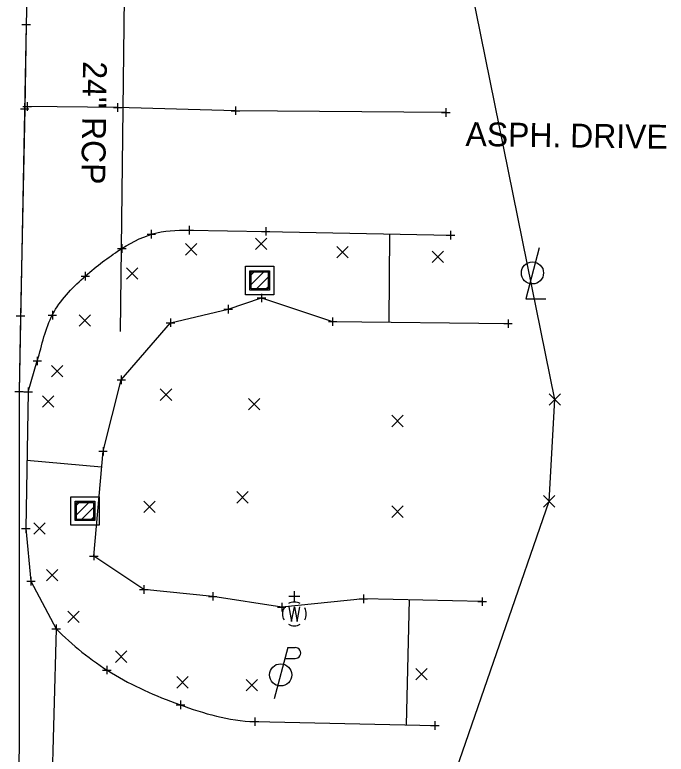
# Model space of a CAD drawing. Extents: x 1392719 to 1392850, y 437833 to 438309.
# Drawn here: x 1392773.1 to 1392849.5, y 437931.1 to 438017.9 of the extents above; entities that cross this region are included whole.
import ezdxf

# ---------------------------------------------------------------- set-up
doc = ezdxf.new("R2010")
doc.units = 0
for name, color, linetype in [('_CIVIL_CONSTRUCTION', 7, 'Continuous'), ('DR_X_Storm_Sewer', 7, 'Continuous'), ('DT_X_Slope_Break_Line', 7, 'Continuous'), ('PV_P_Curb_Ramp', 7, 'Continuous'), ('PV_X_COP', 7, 'Continuous'), ('PV_X_EOP', 7, 'Continuous'), ('RD_P_Fence', 7, 'Continuous'), ('RW_X_Fee_RW', 7, 'Continuous'), ('SC_Scratch6', 7, 'Continuous'), ('SH_Data', 7, 'Continuous'), ('SV_X_Mon_Cells_Found', 7, 'Continuous'), ('SV_X_Terrain_Boundary', 7, 'Continuous'), ('SV_X_Toe_of_Slope', 7, 'Continuous'), ('TX_X_20', 7, 'Continuous')]:
    doc.layers.add(name, color=color, linetype=linetype)

msp = doc.modelspace()

# ---------------------------------------------------------------- linework, layer by layer
at = {"layer": '_CIVIL_CONSTRUCTION'}
for p, q in [((1392805.915, 437948.997), (1392805.915, 437950.269)), ((1392806.55, 437949.634), (1392805.278, 437949.634)), ((1392805.915, 437947.597), (1392805.915, 437947.597))]:
    msp.add_line(p, q, dxfattribs=at)
msp.add_lwpolyline([(1392805.278, 437948.417), (1392805.597, 437946.694), (1392805.915, 437948.417), (1392806.235, 437946.694), (1392806.552, 437948.417)], dxfattribs=at)
for start, end in [(60.01836, 120.01574), (150.01836, 209.98164), (330.01836, 29.98164), (239.98426, 299.98164)]:
    msp.add_arc((1392805.915, 437947.599), 1.4, start, end, dxfattribs=at)
at = {"layer": 'DR_X_Storm_Sewer'}
msp.add_line((1392785.965, 438020.942), (1392785.478, 437980.73), dxfattribs=at)
at = {"layer": 'DT_X_Slope_Break_Line'}
for p, q in [((1392817.078, 437992.184), (1392816.984, 437981.814)), ((1392774.538, 437965.627), (1392783.305, 437964.843)), ((1392819.092, 437934.576), (1392819.418, 437949.247))]:
    msp.add_line(p, q, dxfattribs=at)
at = {"layer": 'PV_P_Curb_Ramp'}
for p, q in [((1392805.161, 437943.652), (1392803.554, 437937.652)), ((1392805.161, 437943.652), (1392806.011, 437943.652)), ((1392804.819, 437942.377), (1392806.011, 437942.377))]:
    msp.add_line(p, q, dxfattribs=at)
msp.add_circle((1392804.304, 437940.452), 1.3, dxfattribs=at)
msp.add_arc((1392806.023, 437943.014), 0.638, 268.8767, 91.1233, dxfattribs=at)
at = {"layer": 'PV_X_COP'}
msp.add_lwpolyline([(1392823.699, 438006.407), (1392799.009, 438006.632), (1392785.176, 438007.01), (1392774.572, 438007.13)], dxfattribs=at)
at = {"layer": 'PV_X_EOP'}
for p, q in [((1392793.579, 437992.61), (1392802.551, 437992.477)), ((1392802.551, 437992.477), (1392824.235, 437992.039)), ((1392774.688, 437973.669), (1392775.756, 437977.274)), ((1392801.259, 437934.966), (1392822.388, 437934.504))]:
    msp.add_line(p, q, dxfattribs=at)
msp.add_lwpolyline([(1392775.84, 438041.527), (1392775.139, 438041.438), (1392774.596, 438023.273), (1392774.455, 438016.732), (1392774.273, 438006.861), (1392773.79, 437982.569), (1392773.613, 437973.697), (1392774.676, 437973.647), (1392774.4, 437957.607), (1392775.011, 437951.431), (1392777.984, 437945.863), (1392777.432, 437925.849), (1392776.728, 437901.157), (1392774.065, 437895.811), (1392773.599, 437888.633)], dxfattribs=at)
for points in [[(1392775.756, 437977.274), (1392776.32, 437979.177), (1392777.048, 437982.962), (1392781.186, 437987.227), (1392785.154, 437990.263), (1392789.266, 437992.519), (1392792.014, 437992.633), (1392793.579, 437992.61)], [(1392777.977, 437945.834), (1392779.814, 437944.001), (1392784.232, 437940.353), (1392792.299, 437936.832), (1392798.232, 437935.032), (1392801.259, 437934.966)]]:
    msp.add_open_spline(points, degree=3, dxfattribs=at)
at = {"layer": 'RD_P_Fence'}
for p, q in [((1392801.365, 437990.332), (1392802.699, 437991.667)), ((1392801.365, 437991.667), (1392802.699, 437990.332)), ((1392793.139, 437989.7), (1392794.473, 437991.035)), ((1392793.139, 437991.035), (1392794.473, 437989.7)), ((1392810.899, 437989.363), (1392812.233, 437990.698)), ((1392810.899, 437990.698), (1392812.233, 437989.363)), ((1392822.068, 437988.807), (1392823.402, 437990.142)), ((1392822.068, 437990.142), (1392823.402, 437988.807)), ((1392786.218, 437986.88), (1392787.552, 437988.215)), ((1392786.218, 437988.215), (1392787.552, 437986.88)), ((1392780.663, 437981.34), (1392781.997, 437982.674)), ((1392780.663, 437982.674), (1392781.997, 437981.34)), ((1392777.426, 437975.426), (1392778.76, 437976.76)), ((1392777.426, 437976.76), (1392778.76, 437975.426)), ((1392790.187, 437972.652), (1392791.521, 437973.987)), ((1392790.187, 437973.987), (1392791.521, 437972.652)), ((1392835.797, 437972.075), (1392837.131, 437973.41)), ((1392835.797, 437973.41), (1392837.131, 437972.075)), ((1392776.361, 437971.85), (1392777.695, 437973.184)), ((1392776.361, 437973.184), (1392777.695, 437971.85)), ((1392800.536, 437971.54), (1392801.87, 437972.874)), ((1392800.536, 437972.874), (1392801.87, 437971.54)), ((1392817.347, 437969.562), (1392818.681, 437970.896)), ((1392817.347, 437970.896), (1392818.681, 437969.562)), ((1392799.17, 437960.611), (1392800.504, 437961.945)), ((1392799.17, 437961.945), (1392800.504, 437960.611)), ((1392835.157, 437960.142), (1392836.491, 437961.477)), ((1392835.157, 437961.477), (1392836.491, 437960.142)), ((1392788.263, 437959.503), (1392789.597, 437960.837)), ((1392788.263, 437960.837), (1392789.597, 437959.503)), ((1392817.334, 437958.927), (1392818.668, 437960.263)), ((1392817.334, 437960.263), (1392818.668, 437958.927)), ((1392775.352, 437956.946), (1392776.686, 437958.281)), ((1392775.352, 437958.281), (1392776.686, 437956.946)), ((1392776.837, 437951.494), (1392778.171, 437952.829)), ((1392776.837, 437952.829), (1392778.171, 437951.494)), ((1392779.335, 437946.601), (1392780.669, 437947.935)), ((1392779.335, 437947.935), (1392780.669, 437946.601)), ((1392784.929, 437941.916), (1392786.263, 437943.252)), ((1392784.929, 437943.252), (1392786.263, 437941.916)), ((1392820.167, 437939.873), (1392821.501, 437941.209)), ((1392820.167, 437941.209), (1392821.501, 437939.873)), ((1392792.136, 437938.911), (1392793.47, 437940.247)), ((1392792.136, 437940.247), (1392793.47, 437938.911)), ((1392800.268, 437938.584), (1392801.602, 437939.918)), ((1392800.268, 437939.918), (1392801.602, 437938.584))]:
    msp.add_line(p, q, dxfattribs=at)
at = {"layer": 'RW_X_Fee_RW'}
for p, q in [((1392800.702, 437986.102), (1392802.461, 437987.861)), ((1392800.702, 437987.233), (1392801.33, 437987.861)), ((1392801.301, 437985.569), (1392802.994, 437987.262)), ((1392802.432, 437985.569), (1392802.994, 437986.131)), ((1392780.209, 437959.074), (1392781.968, 437960.833)), ((1392780.209, 437960.205), (1392780.837, 437960.833)), ((1392780.808, 437958.541), (1392782.501, 437960.234)), ((1392781.939, 437958.541), (1392782.501, 437959.103))]:
    msp.add_line(p, q, dxfattribs=at)
for points in [[(1392800.181, 437988.382), (1392803.515, 437988.382), (1392803.515, 437985.048), (1392800.181, 437985.048)], [(1392800.702, 437987.861), (1392802.994, 437987.861), (1392802.994, 437985.569), (1392800.702, 437985.569)], [(1392800.848, 437987.715), (1392802.848, 437987.715), (1392802.848, 437985.715), (1392800.848, 437985.715)], [(1392779.688, 437961.354), (1392783.022, 437961.354), (1392783.022, 437958.02), (1392779.688, 437958.02)], [(1392780.209, 437960.833), (1392782.501, 437960.833), (1392782.501, 437958.541), (1392780.209, 437958.541)], [(1392780.355, 437960.687), (1392782.355, 437960.687), (1392782.355, 437958.687), (1392780.355, 437958.687)]]:
    msp.add_lwpolyline(points, close=True, dxfattribs=at)
at = {"layer": 'SC_Scratch6'}
for p, q in [((1392773.955, 438016.732), (1392774.955, 438016.732)), ((1392774.455, 438017.232), (1392774.455, 438016.232)), ((1392774.455, 438016.732), (1392774.455, 438016.732)), ((1392774.072, 438007.13), (1392775.072, 438007.13)), ((1392774.273, 438007.361), (1392774.273, 438006.361)), ((1392774.572, 438007.63), (1392774.572, 438006.63)), ((1392774.572, 438007.13), (1392774.572, 438007.13)), ((1392785.176, 438007.51), (1392785.176, 438006.51)), ((1392799.009, 438007.132), (1392799.009, 438006.132)), ((1392773.773, 438006.861), (1392774.773, 438006.861)), ((1392774.273, 438006.861), (1392774.273, 438006.861)), ((1392784.676, 438007.01), (1392785.676, 438007.01)), ((1392785.176, 438007.01), (1392785.176, 438007.01)), ((1392798.509, 438006.632), (1392799.509, 438006.632)), ((1392799.009, 438006.632), (1392799.009, 438006.632)), ((1392823.199, 438006.407), (1392824.199, 438006.407)), ((1392823.699, 438006.907), (1392823.699, 438005.907)), ((1392823.699, 438006.407), (1392823.699, 438006.407)), ((1392789.13, 437992.647), (1392789.13, 437991.647)), ((1392793.079, 437992.61), (1392794.079, 437992.61)), ((1392793.579, 437993.11), (1392793.579, 437992.11)), ((1392793.579, 437992.61), (1392793.579, 437992.61)), ((1392802.051, 437992.477), (1392803.051, 437992.477)), ((1392802.551, 437992.977), (1392802.551, 437991.977)), ((1392802.551, 437992.477), (1392802.551, 437992.477)), ((1392824.235, 437992.539), (1392824.235, 437991.539)), ((1392788.63, 437992.147), (1392789.63, 437992.147)), ((1392789.13, 437992.147), (1392789.13, 437992.147)), ((1392823.735, 437992.039), (1392824.735, 437992.039)), ((1392824.235, 437992.039), (1392824.235, 437992.039)), ((1392785.678, 437990.96), (1392785.678, 437989.96)), ((1392785.178, 437990.46), (1392786.178, 437990.46)), ((1392785.678, 437990.46), (1392785.678, 437990.46)), ((1392780.889, 437987.218), (1392781.889, 437987.218)), ((1392781.389, 437987.718), (1392781.389, 437986.718)), ((1392781.389, 437987.218), (1392781.389, 437987.218)), ((1392801.556, 437984.666), (1392802.556, 437984.666)), ((1392802.056, 437985.166), (1392802.056, 437984.166)), ((1392802.056, 437984.666), (1392802.056, 437984.666)), ((1392798.139, 437983.856), (1392798.139, 437982.856)), ((1392773.79, 437983.069), (1392773.79, 437982.069)), ((1392777.525, 437983.153), (1392777.525, 437982.153)), ((1392797.639, 437983.356), (1392798.639, 437983.356)), ((1392798.139, 437983.356), (1392798.139, 437983.356)), ((1392773.29, 437982.569), (1392774.29, 437982.569)), ((1392773.79, 437982.569), (1392773.79, 437982.569)), ((1392777.025, 437982.653), (1392778.025, 437982.653)), ((1392777.525, 437982.653), (1392777.525, 437982.653)), ((1392791.391, 437982.259), (1392791.391, 437981.259)), ((1392810.405, 437982.388), (1392810.405, 437981.388)), ((1392830.988, 437982.155), (1392830.988, 437981.155)), ((1392790.891, 437981.759), (1392791.891, 437981.759)), ((1392791.391, 437981.759), (1392791.391, 437981.759)), ((1392809.905, 437981.888), (1392810.905, 437981.888)), ((1392810.405, 437981.888), (1392810.405, 437981.888)), ((1392830.488, 437981.655), (1392831.488, 437981.655)), ((1392830.988, 437981.655), (1392830.988, 437981.655)), ((1392775.756, 437977.774), (1392775.756, 437976.774)), ((1392775.256, 437977.274), (1392776.256, 437977.274)), ((1392775.756, 437977.274), (1392775.756, 437977.274)), ((1392785.11, 437975.049), (1392786.11, 437975.049)), ((1392785.61, 437975.549), (1392785.61, 437974.549)), ((1392785.61, 437975.049), (1392785.61, 437975.049)), ((1392773.613, 437974.197), (1392773.613, 437973.197)), ((1392774.676, 437974.147), (1392774.676, 437973.147)), ((1392774.688, 437974.169), (1392774.688, 437973.169)), ((1392773.113, 437973.697), (1392774.113, 437973.697)), ((1392773.613, 437973.697), (1392773.613, 437973.697)), ((1392774.176, 437973.647), (1392775.176, 437973.647)), ((1392774.188, 437973.669), (1392775.188, 437973.669)), ((1392774.676, 437973.647), (1392774.676, 437973.647)), ((1392774.688, 437973.669), (1392774.688, 437973.669)), ((1392783.468, 437967.179), (1392783.468, 437966.179)), ((1392782.968, 437966.679), (1392783.968, 437966.679)), ((1392783.468, 437966.679), (1392783.468, 437966.679)), ((1392774.4, 437958.107), (1392774.4, 437957.107)), ((1392773.9, 437957.607), (1392774.9, 437957.607)), ((1392774.4, 437957.607), (1392774.4, 437957.607)), ((1392781.878, 437954.39), (1392782.878, 437954.39)), ((1392782.378, 437954.89), (1392782.378, 437953.89)), ((1392782.378, 437954.39), (1392782.378, 437954.39)), ((1392775.011, 437951.931), (1392775.011, 437950.931)), ((1392774.511, 437951.431), (1392775.511, 437951.431)), ((1392775.011, 437951.431), (1392775.011, 437951.431)), ((1392788.261, 437950.964), (1392788.261, 437949.964)), ((1392787.761, 437950.464), (1392788.761, 437950.464)), ((1392788.261, 437950.464), (1392788.261, 437950.464)), ((1392796.338, 437950.164), (1392796.338, 437949.164)), ((1392814.013, 437949.876), (1392814.013, 437948.876)), ((1392795.838, 437949.664), (1392796.838, 437949.664)), ((1392796.338, 437949.664), (1392796.338, 437949.664)), ((1392813.513, 437949.376), (1392814.513, 437949.376)), ((1392814.013, 437949.376), (1392814.013, 437949.376)), ((1392827.451, 437949.043), (1392828.451, 437949.043)), ((1392827.951, 437949.543), (1392827.951, 437948.543)), ((1392827.951, 437949.043), (1392827.951, 437949.043)), ((1392803.928, 437948.39), (1392804.928, 437948.39)), ((1392804.428, 437948.89), (1392804.428, 437947.89)), ((1392804.428, 437948.39), (1392804.428, 437948.39)), ((1392777.984, 437946.363), (1392777.984, 437945.363)), ((1392777.477, 437945.834), (1392778.477, 437945.834)), ((1392777.484, 437945.863), (1392778.484, 437945.863)), ((1392777.977, 437946.334), (1392777.977, 437945.334)), ((1392777.977, 437945.834), (1392777.977, 437945.834)), ((1392777.984, 437945.863), (1392777.984, 437945.863)), ((1392783.918, 437941.521), (1392783.918, 437940.521)), ((1392783.418, 437941.021), (1392784.418, 437941.021)), ((1392783.918, 437941.021), (1392783.918, 437941.021)), ((1392792.051, 437936.933), (1392793.051, 437936.933)), ((1392792.551, 437937.433), (1392792.551, 437936.433)), ((1392792.551, 437936.933), (1392792.551, 437936.933)), ((1392801.259, 437935.466), (1392801.259, 437934.466)), ((1392800.759, 437934.966), (1392801.759, 437934.966)), ((1392801.259, 437934.966), (1392801.259, 437934.966)), ((1392821.888, 437934.504), (1392822.888, 437934.504)), ((1392822.388, 437935.004), (1392822.388, 437934.004)), ((1392822.388, 437934.504), (1392822.388, 437934.504))]:
    msp.add_line(p, q, dxfattribs=at)
at = {"layer": 'SH_Data'}
msp.add_lwpolyline([(1392834.64, 437990.554), (1392833.065, 437984.569), (1392835.428, 437984.569)], dxfattribs=at)
msp.add_circle((1392833.853, 437987.601), 1.3, dxfattribs=at)
at = {"layer": 'SV_X_Mon_Cells_Found'}
for p, q in [((1392801.848, 437988.382), (1392801.848, 437988.382)), ((1392801.848, 437987.715), (1392801.848, 437987.715)), ((1392800.848, 437986.715), (1392800.848, 437986.715)), ((1392801.848, 437986.715), (1392801.848, 437986.715)), ((1392801.848, 437986.715), (1392801.848, 437986.715)), ((1392801.848, 437986.715), (1392801.848, 437986.715)), ((1392802.848, 437986.715), (1392802.848, 437986.715)), ((1392801.848, 437985.715), (1392801.848, 437985.715)), ((1392801.848, 437985.048), (1392801.848, 437985.048)), ((1392781.355, 437961.354), (1392781.355, 437961.354)), ((1392781.355, 437960.687), (1392781.355, 437960.687)), ((1392780.355, 437959.687), (1392780.355, 437959.687)), ((1392781.355, 437959.687), (1392781.355, 437959.687)), ((1392781.355, 437959.687), (1392781.355, 437959.687)), ((1392781.355, 437959.687), (1392781.355, 437959.687)), ((1392782.355, 437959.687), (1392782.355, 437959.687)), ((1392781.355, 437958.687), (1392781.355, 437958.687)), ((1392781.355, 437958.02), (1392781.355, 437958.02))]:
    msp.add_line(p, q, dxfattribs=at)
at = {"layer": 'SV_X_Terrain_Boundary'}
msp.add_lwpolyline([(1392773.599, 437888.633), (1392814.061, 437897.949), (1392835.824, 437960.81), (1392836.464, 437972.743), (1392818.576, 438061.039), (1392787.876, 438062.949), (1392775.139, 438041.438), (1392774.596, 438023.273), (1392774.455, 438016.732), (1392773.613, 437973.697)], close=True, dxfattribs=at)
at = {"layer": 'SV_X_Toe_of_Slope'}
msp.add_lwpolyline([(1392827.951, 437949.043), (1392814.013, 437949.376), (1392804.428, 437948.39), (1392796.338, 437949.664), (1392788.261, 437950.464), (1392782.378, 437954.39), (1392783.468, 437966.679), (1392785.61, 437975.049), (1392791.391, 437981.759), (1392798.139, 437983.356), (1392802.056, 437984.666), (1392810.405, 437981.888), (1392830.988, 437981.655)], dxfattribs=at)

# ---------------------------------------------------------------- texts
at = {"layer": 'TX_X_20'}
for s, height, rotation, p in [('24" RCP', 2.8, 269.16965, (1392781.123, 438012.439)), ('ASPH. DRIVE', 2.79999, 359.16965, (1392825.985, 438002.501))]:
    msp.add_text(s, height=height, rotation=rotation, dxfattribs=at).set_placement(p)

doc.saveas('drawing.dxf')
